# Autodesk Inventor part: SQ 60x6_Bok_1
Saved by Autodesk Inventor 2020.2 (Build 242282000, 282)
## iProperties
Created: 2006-08
Part Number: SQ 60x6_Bok_1
Material: Ogólny
Document SubType Name: Modeling
Designer: F.Stasiak
Manufacturer: Standard
Standards Organization: Custom
Stock Number: DIN EN 10210-2 SQ 60x6
Density: 1 g/cm^3
Appearance: Domyślna
Manager: www.cadconsulting.pl
Company: Fabian Stasiak CAD Consulting
G_L: 500,0 mm
G_W: 60,000 mm
G_H: 60,000 mm
AFG_Item: 60 x 60 x 6
Author: F.Stasiak
Subject: Zbiór ćwiczeń. Autodesk Inventor 2020. Kurs podstawowy
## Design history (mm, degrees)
sketch "AFG_Detailed"
  geometry: L1 (48, 54)-(12, 54); L2 (6, 48)-(6, 12); L3 (12, 6)-(48, 6); L4 (54, 12)-(54, 48); L5 (48, 60)-(12, 60); L6 (0, 48)-(0, 12); L7 (12, 0)-(48, 0); L8 (60, 12)-(60, 48); A1 r 6 centre (48, 48) between (54, 48) and (48, 54); A2 r 12 centre (48, 48) between (60, 48) and (48, 60); A3 r 6 centre (48, 12) between (48, 6) and (54, 12); A4 r 12 centre (48, 12) between (48, 0) and (60, 12); A5 r 12 centre (12, 12) between (0, 12) and (12, 0); A6 r 6 centre (12, 12) between (6, 12) and (12, 6); A7 r 6 centre (12, 48) between (12, 54) and (6, 48); A8 r 12 centre (12, 48) between (12, 60) and (0, 48); 4 further points
  constraints: 16 end point, 16 point on circle, 16 tangent, 8 centre point, 6 point on line, 4 parallel, 2 perpendicular, 1 vertical
  dimensions: "d15" = 60 distance of point (0, 0) point (60, 0) (= GEO_B); "d16" = 6 distance between parallel lines of L7 L3 (= GEO_S); "d17" = 6 distance between parallel lines of L8 L4 (= GEO_S); "d18" = 6 distance between parallel lines of L5 L1 (= GEO_S); "d19" = 6 distance between parallel lines of L6 L2 (= GEO_S); "d20" = 30 distance from line of point (30, 30) L7 (= 0.5 x GEO_H); "d30" = 6 radius of A1 (= GEO_R1 - GEO_S); "GEO_R1" = 12 radius of A2; "d32" = 6 radius of A3 (= GEO_R1 - GEO_S); "d33" = 12 radius of A4 (= GEO_R1); "d34" = 12 radius of A5 (= GEO_R1); "d35" = 6 radius of A6 (= GEO_R1 - GEO_S); "d36" = 6 radius of A7 (= GEO_R1 - GEO_S); "d37" = 12 radius of A8 (= GEO_R1); "d38" = 30 distance from line of L6 point (30, 30) (= 0.5 x GEO_B); "d39" = 60 distance between parallel lines of L7 L5 (= GEO_H)
sketch "AFG_Medium"
  geometry: L1 (54, 54)-(6, 54); L2 (6, 54)-(6, 6); L3 (6, 6)-(54, 6); L4 (54, 6)-(54, 54); L5 (60, 60)-(0, 60); L6 (0, 60)-(0, 0); L7 (0, 0)-(60, 0); L8 (60, 0)-(60, 60); 1 further point
  constraints: 16 end point, 4 parallel, 2 perpendicular, 1 vertical
  dimensions: "GEO_B" = 60 distance of L6.end L7.end; "GEO_S" = 6 distance between parallel lines of L7 L3; "d5" = 6 distance between parallel lines of L8 L4 (= GEO_S); "d6" = 6 distance between parallel lines of L5 L1 (= GEO_S); "d7" = 6 distance between parallel lines of L6 L2 (= GEO_S); "d12" = 30 distance from line of point (30, 30) L7 (= 0.5 x GEO_H); "d40" = 60 distance between parallel lines of L7 L5 (= GEO_H); "d41" = 30 distance from line of L6 point (30, 30) (= 0.5 x GEO_B)
sketch "AFG_Simplified"
  geometry: L1 (60, 60)-(0, 60); L2 (0, 60)-(0, 0); L3 (0, 0)-(60, 0); L4 (60, 0)-(60, 60); 1 further point
  constraints: 8 end point, 2 parallel, 1 perpendicular, 1 vertical
  dimensions: "d23" = 60 distance of L2.end L3.end (= GEO_B); "d28" = 30 distance from line of point (30, 30) L3 (= 0.5 x GEO_H); "d42" = 60 distance between parallel lines of L3 L1 (= GEO_H); "d43" = 30 distance from line of point (30, 30) L2 (= 0.5 x GEO_B)
derived "Szkielet podstawy.ipt"
  sketch "Szkic1"
    geometry: L1 (0, 0)-(1500, 0) reference; L2 (1500, 0)-(1500, 1000) reference; L3 (1500, 1000)-(0, 1000) reference; L4 (0, 1000)-(0, 0) reference
  sketch "Szkic2"
    geometry: L1 (0, 1000)-(0, 0) reference; L2 (0, 0)-(1500, 0) reference; L3 (1500, 0)-(1500, 1000) reference; L4 (500, 1000)-(1500, 1000) reference; L5 (1500, 1000)-(1500, 0) reference; L6 (1500, 0)-(500, 0) reference; L7 (500, 0)-(500, 1000) reference; L8 (1500, 1000)-(0, 1000) reference
node "AFG_StartWorkPoint_SQ 60x6_Bok_1"
node "AFG_EndWorkPoint_SQ 60x6_Bok_1"
node "AFG_HelpAxis"
node "AFG_HelpStart"
node "AFG_HelpEnd"
node "AFG_Midplane"
  node "AFG_Startplane"
  node "AFG_EndPlane"
node "AFG_Profile_AxisX_for_External_Matrix"
extrude "AFG_Detailed_SQ 60x6_Bok_1" join sketch "AFG_Detailed" stored distance "d49" = 0.13; taper "d50" = 0 deg
extrude "AFG_Simplified_SQ 60x6_Bok_1" join sketch "AFG_Simplified" stored distance "d51" = 0.13; taper "d52" = 0 deg
node "Bryła1"
node "Korpusy bryłowe"
node "Korpusy powierzchniowe"
other parameters: "GEO_H" = 60, "AFG_Origin_X" = 0 (= 0 x GEO_B) [user parameter], "AFG_Origin_Y" = 0 (= 0 x GEO_H) [user parameter], "AFG_IP_X2" = 0 (= 0 x GEO_B) [user parameter], "AFG_IP_Y4" = 0 (= 0 x GEO_H) [user parameter], "AFG_IP_X6" = 0 (= 0 x GEO_B) [user parameter], "AFG_IP_Y8" = 0 (= 0 x GEO_H) [user parameter], "d47" = 0, "d48" = 0, "G_L" = 500 [user parameter]
